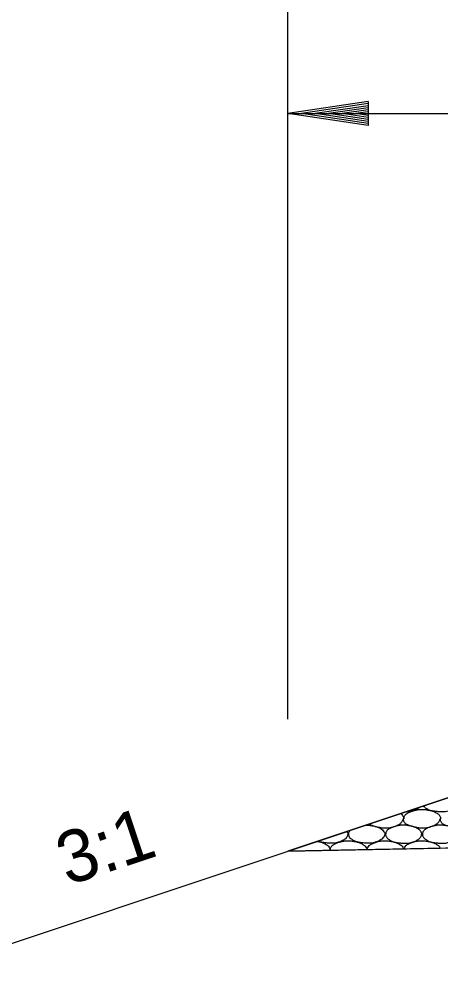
# Model space of a CAD drawing. Extents: x 1373719 to 1374161, y 379835 to 380167.
# Drawn here: x 1373935.35 to 1373940.61, y 379972.17 to 379984.17 of the extents above; entities that cross this region are included whole.
import ezdxf

# ---------------------------------------------------------------- set-up
doc = ezdxf.new("R2010")
doc.units = 0
for name, color, linetype in [('Aggregate Base Course', 7, 'Continuous'), ('GREEN_TXT', 7, 'Continuous'), ('SIGNATURE', 7, 'Continuous')]:
    doc.layers.add(name, color=color, linetype=linetype)

msp = doc.modelspace()

# ---------------------------------------------------------------- linework, layer by layer
for p, q in [((1373933.855, 379972.169), (1373945.855, 379976.169)), ((1373965.355, 379974.318), (1373938.705, 379973.785))]:
    msp.add_line(p, q)
at = {"layer": 'Aggregate Base Course'}
for points, degree in [([(1373940.76, 379974.47), (1373940.767, 379974.467), (1373940.775, 379974.463), (1373940.802, 379974.449), (1373940.816, 379974.434), (1373940.835, 379974.406), (1373940.838, 379974.396), (1373940.833, 379974.37), (1373940.824, 379974.354), (1373940.803, 379974.329), (1373940.794, 379974.323), (1373940.766, 379974.307), (1373940.748, 379974.298), (1373940.703, 379974.284), (1373940.677, 379974.277), (1373940.638, 379974.275), (1373940.624, 379974.275), (1373940.591, 379974.277), (1373940.572, 379974.279), (1373940.53, 379974.284), (1373940.509, 379974.287), (1373940.469, 379974.296), (1373940.454, 379974.305), (1373940.423, 379974.325), (1373940.41, 379974.335), (1373940.398, 379974.35)], 3), ([(1373940.156, 379974.191), (1373940.156, 379974.192), (1373940.156, 379974.192), (1373940.156, 379974.193), (1373940.156, 379974.208), (1373940.16, 379974.223), (1373940.17, 379974.236), (1373940.18, 379974.25), (1373940.192, 379974.258), (1373940.206, 379974.265), (1373940.218, 379974.271), (1373940.23, 379974.277), (1373940.242, 379974.281), (1373940.26, 379974.287), (1373940.278, 379974.293), (1373940.296, 379974.297), (1373940.308, 379974.3), (1373940.319, 379974.303), (1373940.33, 379974.305), (1373940.347, 379974.307), (1373940.364, 379974.308), (1373940.381, 379974.306)], 3), ([(1373940.343, 379974.331), (1373940.337, 379974.326), (1373940.33, 379974.321), (1373940.305, 379974.307), (1373940.287, 379974.298), (1373940.242, 379974.284), (1373940.216, 379974.277), (1373940.185, 379974.275), (1373940.18, 379974.275), (1373940.175, 379974.275)], 3), ([(1373940.381, 379974.306), (1373940.383, 379974.306), (1373940.384, 379974.306), (1373940.386, 379974.306)], 2), ([(1373940.386, 379974.306), (1373940.413, 379974.307), (1373940.439, 379974.303), (1373940.465, 379974.297), (1373940.498, 379974.291), (1373940.527, 379974.281), (1373940.557, 379974.265), (1373940.577, 379974.254), (1373940.593, 379974.24), (1373940.604, 379974.22), (1373940.609, 379974.211), (1373940.61, 379974.202), (1373940.611, 379974.193), (1373940.611, 379974.192), (1373940.611, 379974.192), (1373940.611, 379974.191)], 3), ([(1373940.14, 379974.191), (1373940.14, 379974.189), (1373940.14, 379974.188), (1373940.14, 379974.186), (1373940.139, 379974.168), (1373940.127, 379974.152), (1373940.114, 379974.137), (1373940.106, 379974.128), (1373940.098, 379974.121), (1373940.087, 379974.116), (1373940.069, 379974.105), (1373940.051, 379974.097), (1373940.032, 379974.09), (1373940.006, 379974.082), (1373939.981, 379974.075), (1373939.954, 379974.074), (1373939.943, 379974.074), (1373939.931, 379974.074), (1373939.92, 379974.074)], 3), ([(1373940.113, 379974.255), (1373940.125, 379974.246), (1373940.135, 379974.234), (1373940.148, 379974.211), (1373940.15, 379974.202), (1373940.15, 379974.192), (1373940.151, 379974.192), (1373940.15, 379974.191)], 3), ([(1373940.381, 379974.074), (1373940.378, 379974.074), (1373940.376, 379974.074), (1373940.374, 379974.074), (1373940.354, 379974.074), (1373940.334, 379974.076), (1373940.314, 379974.08), (1373940.293, 379974.083), (1373940.273, 379974.09), (1373940.253, 379974.096), (1373940.235, 379974.101), (1373940.218, 379974.106), (1373940.201, 379974.114), (1373940.182, 379974.122), (1373940.166, 379974.136), (1373940.156, 379974.155), (1373940.151, 379974.165), (1373940.149, 379974.175), (1373940.149, 379974.186), (1373940.149, 379974.188), (1373940.149, 379974.189), (1373940.149, 379974.191)], 3), ([(1373940.6, 379974.191), (1373940.6, 379974.189), (1373940.6, 379974.188), (1373940.6, 379974.186), (1373940.6, 379974.168), (1373940.588, 379974.152), (1373940.575, 379974.137), (1373940.567, 379974.128), (1373940.558, 379974.121), (1373940.548, 379974.116), (1373940.53, 379974.105), (1373940.512, 379974.097), (1373940.492, 379974.09), (1373940.467, 379974.082), (1373940.441, 379974.075), (1373940.415, 379974.074), (1373940.404, 379974.074), (1373940.392, 379974.074), (1373940.381, 379974.074)], 3), ([(1373940.842, 379974.074), (1373940.839, 379974.074), (1373940.837, 379974.074), (1373940.834, 379974.074), (1373940.815, 379974.074), (1373940.795, 379974.076), (1373940.775, 379974.08), (1373940.754, 379974.083), (1373940.734, 379974.09), (1373940.713, 379974.096), (1373940.696, 379974.101), (1373940.679, 379974.106), (1373940.662, 379974.114), (1373940.643, 379974.122), (1373940.627, 379974.136), (1373940.617, 379974.155), (1373940.611, 379974.165), (1373940.609, 379974.175), (1373940.609, 379974.186), (1373940.609, 379974.188), (1373940.609, 379974.189), (1373940.609, 379974.191)], 3), ([(1373939.69, 379974.11), (1373939.716, 379974.111), (1373939.742, 379974.107), (1373939.801, 379974.095), (1373939.831, 379974.085), (1373939.881, 379974.058), (1373939.894, 379974.044), (1373939.913, 379974.015), (1373939.916, 379974.005), (1373939.912, 379973.98), (1373939.903, 379973.963), (1373939.881, 379973.939), (1373939.873, 379973.932), (1373939.844, 379973.916), (1373939.826, 379973.908), (1373939.781, 379973.893), (1373939.756, 379973.887), (1373939.716, 379973.884), (1373939.703, 379973.884), (1373939.67, 379973.886), (1373939.65, 379973.888), (1373939.608, 379973.893), (1373939.587, 379973.896), (1373939.548, 379973.905), (1373939.533, 379973.915), (1373939.499, 379973.936), (1373939.484, 379973.947), (1373939.465, 379973.976), (1373939.464, 379973.987), (1373939.465, 379974.011), (1373939.469, 379974.026), (1373939.48, 379974.042), (1373939.481, 379974.043), (1373939.483, 379974.045)], 3), ([(1373939.681, 379974.111), (1373939.684, 379974.111), (1373939.687, 379974.11), (1373939.69, 379974.11)], 2), ([(1373939.92, 379974.074), (1373939.918, 379974.074), (1373939.915, 379974.074), (1373939.893, 379974.074), (1373939.873, 379974.076), (1373939.832, 379974.083), (1373939.812, 379974.09), (1373939.774, 379974.101), (1373939.757, 379974.106), (1373939.733, 379974.117), (1373939.727, 379974.12), (1373939.722, 379974.124)], 3), ([(1373940.15, 379974.11), (1373940.177, 379974.111), (1373940.203, 379974.107), (1373940.23, 379974.101), (1373940.262, 379974.095), (1373940.292, 379974.085), (1373940.321, 379974.069), (1373940.341, 379974.058), (1373940.355, 379974.044), (1373940.368, 379974.024), (1373940.374, 379974.015), (1373940.377, 379974.005), (1373940.375, 379973.997), (1373940.372, 379973.98), (1373940.364, 379973.963), (1373940.35, 379973.948), (1373940.342, 379973.939), (1373940.333, 379973.932), (1373940.323, 379973.927), (1373940.305, 379973.916), (1373940.287, 379973.908), (1373940.267, 379973.901), (1373940.242, 379973.893), (1373940.216, 379973.887), (1373940.19, 379973.885), (1373940.177, 379973.884), (1373940.164, 379973.884), (1373940.15, 379973.885), (1373940.131, 379973.886), (1373940.111, 379973.888), (1373940.091, 379973.891), (1373940.069, 379973.893), (1373940.048, 379973.896), (1373940.026, 379973.901), (1373940.009, 379973.905), (1373939.993, 379973.915), (1373939.978, 379973.925), (1373939.96, 379973.936), (1373939.945, 379973.947), (1373939.933, 379973.966), (1373939.926, 379973.976), (1373939.925, 379973.987), (1373939.925, 379973.997), (1373939.926, 379974.011), (1373939.929, 379974.026), (1373939.94, 379974.04), (1373939.95, 379974.054), (1373939.962, 379974.062), (1373939.976, 379974.069), (1373939.988, 379974.075), (1373939.999, 379974.081), (1373940.012, 379974.085), (1373940.03, 379974.091), (1373940.048, 379974.096), (1373940.066, 379974.101), (1373940.077, 379974.104), (1373940.088, 379974.107), (1373940.1, 379974.108), (1373940.117, 379974.111), (1373940.134, 379974.112), (1373940.15, 379974.11)], 3), ([(1373940.611, 379974.11), (1373940.638, 379974.111), (1373940.664, 379974.107), (1373940.69, 379974.101), (1373940.723, 379974.095), (1373940.752, 379974.085), (1373940.782, 379974.069), (1373940.802, 379974.058), (1373940.816, 379974.044), (1373940.829, 379974.024), (1373940.835, 379974.015), (1373940.838, 379974.005), (1373940.836, 379973.997), (1373940.833, 379973.98), (1373940.824, 379973.963), (1373940.811, 379973.948), (1373940.803, 379973.939), (1373940.794, 379973.932), (1373940.784, 379973.927), (1373940.766, 379973.916), (1373940.748, 379973.908), (1373940.728, 379973.901), (1373940.703, 379973.893), (1373940.677, 379973.887), (1373940.651, 379973.885), (1373940.638, 379973.884), (1373940.624, 379973.884), (1373940.611, 379973.885), (1373940.591, 379973.886), (1373940.572, 379973.888), (1373940.552, 379973.891), (1373940.53, 379973.893), (1373940.509, 379973.896), (1373940.487, 379973.901), (1373940.469, 379973.905), (1373940.454, 379973.915), (1373940.438, 379973.925), (1373940.421, 379973.936), (1373940.406, 379973.947), (1373940.393, 379973.966), (1373940.387, 379973.976), (1373940.386, 379973.987), (1373940.386, 379973.997), (1373940.387, 379974.011), (1373940.39, 379974.026), (1373940.401, 379974.04), (1373940.411, 379974.054), (1373940.423, 379974.062), (1373940.437, 379974.069), (1373940.448, 379974.075), (1373940.46, 379974.081), (1373940.473, 379974.085), (1373940.49, 379974.091), (1373940.508, 379974.096), (1373940.527, 379974.101), (1373940.538, 379974.104), (1373940.549, 379974.107), (1373940.561, 379974.108), (1373940.577, 379974.111), (1373940.595, 379974.112), (1373940.611, 379974.11)], 3), ([(1373939.442, 379974.031), (1373939.443, 379974.029), (1373939.445, 379974.026), (1373939.452, 379974.015), (1373939.455, 379974.005), (1373939.451, 379973.98), (1373939.442, 379973.963), (1373939.42, 379973.939), (1373939.412, 379973.932), (1373939.383, 379973.916), (1373939.366, 379973.908), (1373939.32, 379973.893), (1373939.295, 379973.887), (1373939.255, 379973.884), (1373939.242, 379973.884), (1373939.209, 379973.886), (1373939.189, 379973.888), (1373939.148, 379973.893), (1373939.126, 379973.896), (1373939.096, 379973.903), (1373939.088, 379973.907), (1373939.08, 379973.91)], 3), ([(1373939.074, 379973.908), (1373939.077, 379973.908), (1373939.08, 379973.907), (1373939.115, 379973.9), (1373939.145, 379973.89), (1373939.195, 379973.864), (1373939.211, 379973.85), (1373939.226, 379973.821), (1373939.228, 379973.812), (1373939.229, 379973.802), (1373939.229, 379973.801), (1373939.229, 379973.801)], 3), ([(1373939.234, 379973.801), (1373939.234, 379973.801), (1373939.234, 379973.802), (1373939.234, 379973.802), (1373939.235, 379973.818), (1373939.239, 379973.832), (1373939.249, 379973.846), (1373939.259, 379973.859), (1373939.271, 379973.867), (1373939.285, 379973.874), (1373939.296, 379973.881), (1373939.308, 379973.886), (1373939.321, 379973.891), (1373939.338, 379973.897), (1373939.356, 379973.902), (1373939.375, 379973.907), (1373939.386, 379973.91), (1373939.397, 379973.912), (1373939.409, 379973.914), (1373939.425, 379973.917), (1373939.443, 379973.917), (1373939.459, 379973.916)], 3), ([(1373939.459, 379973.916), (1373939.461, 379973.916), (1373939.463, 379973.916), (1373939.465, 379973.916)], 2), ([(1373939.465, 379973.916), (1373939.491, 379973.916), (1373939.517, 379973.912), (1373939.576, 379973.9), (1373939.606, 379973.89), (1373939.656, 379973.864), (1373939.671, 379973.85), (1373939.687, 379973.821), (1373939.689, 379973.813), (1373939.689, 379973.805)], 3), ([(1373939.695, 379973.805), (1373939.696, 379973.819), (1373939.7, 379973.833), (1373939.719, 379973.859), (1373939.732, 379973.867), (1373939.757, 379973.881), (1373939.769, 379973.886), (1373939.799, 379973.897), (1373939.817, 379973.902), (1373939.847, 379973.91), (1373939.858, 379973.912), (1373939.886, 379973.917), (1373939.903, 379973.917), (1373939.92, 379973.916)], 3), ([(1373939.92, 379973.916), (1373939.922, 379973.916), (1373939.924, 379973.916), (1373939.925, 379973.916)], 2), ([(1373939.925, 379973.916), (1373939.952, 379973.916), (1373939.978, 379973.912), (1373940.037, 379973.9), (1373940.067, 379973.89), (1373940.116, 379973.864), (1373940.132, 379973.85), (1373940.146, 379973.824), (1373940.148, 379973.819), (1373940.149, 379973.814)], 3), ([(1373940.157, 379973.814), (1373940.159, 379973.825), (1373940.163, 379973.836), (1373940.18, 379973.859), (1373940.192, 379973.867), (1373940.218, 379973.881), (1373940.23, 379973.886), (1373940.26, 379973.897), (1373940.278, 379973.902), (1373940.308, 379973.91), (1373940.319, 379973.912), (1373940.347, 379973.917), (1373940.364, 379973.917), (1373940.381, 379973.916)], 3), ([(1373940.381, 379973.916), (1373940.383, 379973.916), (1373940.384, 379973.916), (1373940.386, 379973.916)], 2), ([(1373940.386, 379973.916), (1373940.413, 379973.916), (1373940.439, 379973.912), (1373940.498, 379973.9), (1373940.527, 379973.89), (1373940.577, 379973.864), (1373940.593, 379973.85), (1373940.605, 379973.827), (1373940.606, 379973.825), (1373940.607, 379973.823)], 3), ([(1373938.757, 379973.801), (1373938.757, 379973.799), (1373938.757, 379973.797), (1373938.757, 379973.792), (1373938.757, 379973.789), (1373938.756, 379973.786)], 3), ([(1373938.767, 379973.787), (1373938.766, 379973.789), (1373938.766, 379973.792), (1373938.766, 379973.797), (1373938.766, 379973.799), (1373938.766, 379973.801)], 3), ([(1373938.768, 379973.806), (1373938.768, 379973.805), (1373938.768, 379973.804), (1373938.768, 379973.802), (1373938.768, 379973.801), (1373938.768, 379973.801)], 3), ([(1373938.773, 379973.801), (1373938.773, 379973.801), (1373938.773, 379973.802), (1373938.773, 379973.804), (1373938.774, 379973.806), (1373938.774, 379973.808)], 3), ([(1373939.218, 379973.801), (1373939.218, 379973.799), (1373939.218, 379973.797), (1373939.218, 379973.796)], 2), ([(1373939.227, 379973.796), (1373939.227, 379973.797), (1373939.227, 379973.799), (1373939.227, 379973.801)], 2)]:
    msp.add_open_spline(points, degree=degree, dxfattribs=at)
at = {"layer": 'GREEN_TXT'}
for p, q in [((1373938.705, 379975.434), (1373938.705, 379989.371)), ((1373939.705, 379983.142), (1373938.705, 379982.992)), ((1373939.705, 379983.117), (1373938.872, 379982.992)), ((1373939.705, 379983.091), (1373939.044, 379982.992)), ((1373939.705, 379983.066), (1373939.21, 379982.992)), ((1373939.705, 379983.142), (1373939.705, 379982.842)), ((1373938.705, 379982.992), (1373945.855, 379982.992)), ((1373939.705, 379982.842), (1373938.705, 379982.992)), ((1373939.705, 379982.867), (1373938.872, 379982.992)), ((1373939.705, 379982.892), (1373939.044, 379982.992)), ((1373939.705, 379982.917), (1373939.21, 379982.992)), ((1373939.705, 379983.04), (1373939.38, 379982.992)), ((1373939.705, 379982.943), (1373939.38, 379982.992)), ((1373939.705, 379983.015), (1373939.547, 379982.992)), ((1373939.705, 379982.968), (1373939.547, 379982.992))]:
    msp.add_line(p, q, dxfattribs=at)
at = {"layer": 'SIGNATURE'}
msp.add_lwpolyline([(1373946.755, 379975.834), (1373945.855, 379975.798), (1373946.24, 379976.184), (1373945.855, 379976.169), (1373943.69, 379975.447), (1373938.705, 379973.785), (1373947.595, 379973.963), (1373946.755, 379975.834)], dxfattribs=at)

# ---------------------------------------------------------------- texts
at = {"layer": 'GREEN_TXT'}
msp.add_text('3:1', height=0.65, rotation=18.4349, dxfattribs=at).set_placement((1373935.951, 379973.353))

doc.saveas('drawing.dxf')
